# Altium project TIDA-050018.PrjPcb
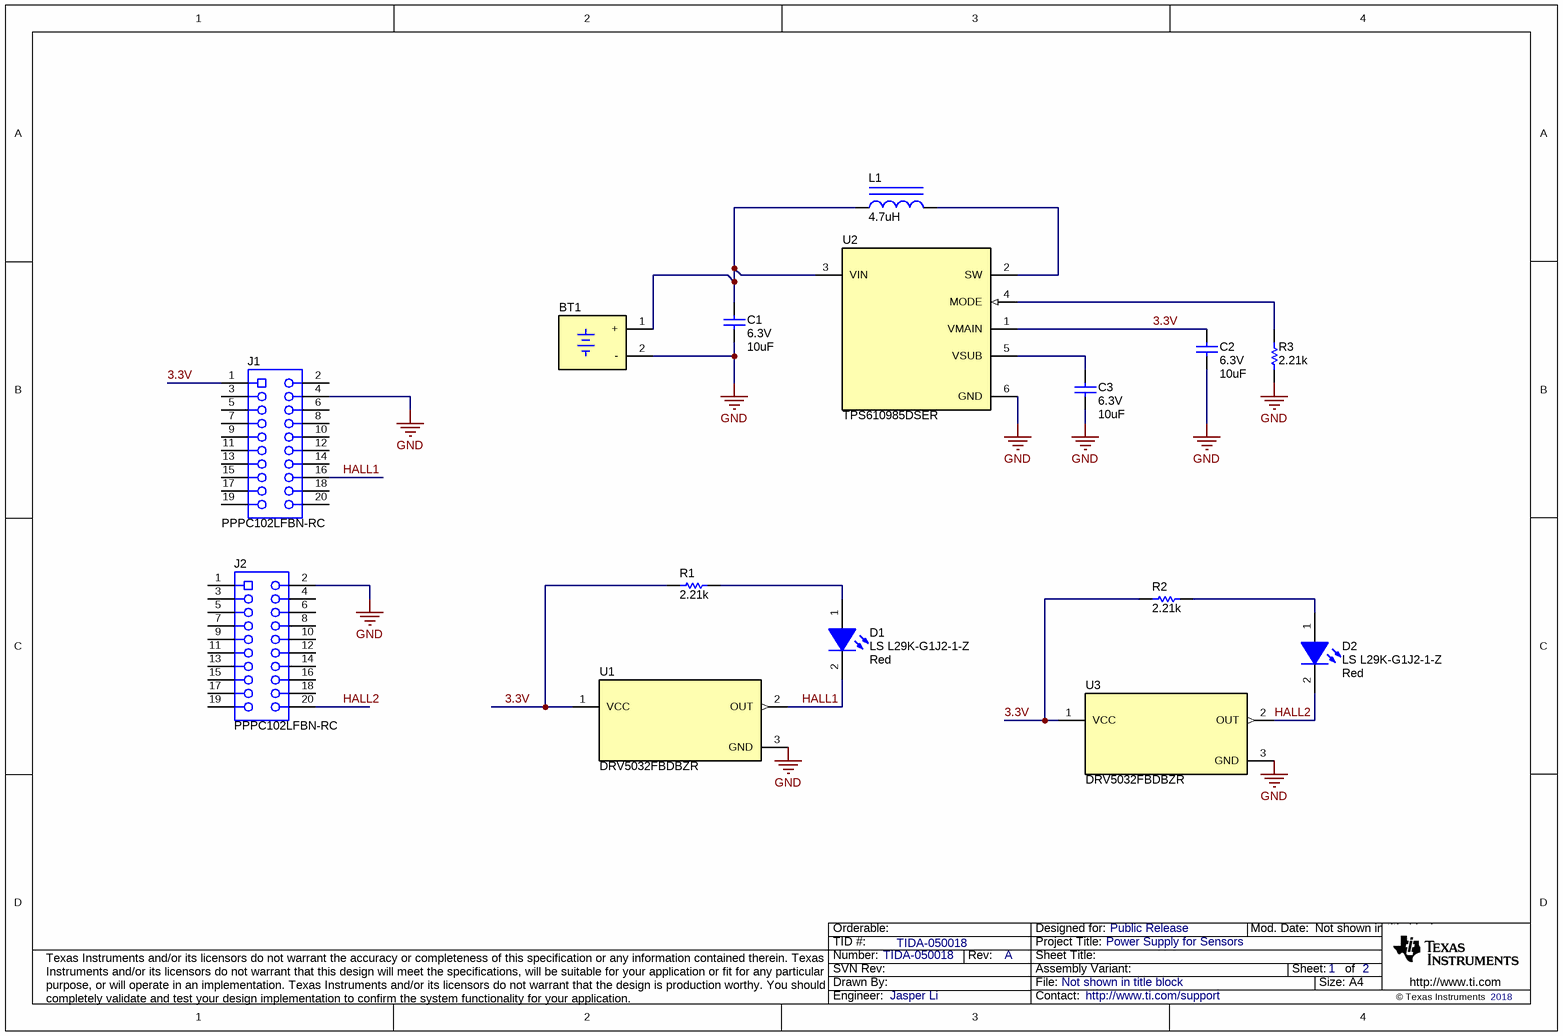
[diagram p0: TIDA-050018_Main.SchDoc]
CopyrightYear: 2018; PCB_Layout: Jasper Li; PCB_Rev: A; PRJ_Customer: Public Release; PRJ_Engineer: Jasper Li; PRJ_Number: TIDA-050018; PRJ_Title: Power Supply for Sensors; SCH_Rev: A; TechSupport: http://www.ti.com/support; TID: TIDA-050018
2 sheets, 20 parts. Net scope: global (net labels, ports and power ports of the same name join across sheets).
Board file: TIDA-050018_PCB.PcbDoc
Sheets:
  TIDA-050018_Main.SchDoc
  TIDA-050018_Hardware.SchDoc

## Sheet TIDA-050018_Main.SchDoc
size A4; Date: Not shown in title block; ApprovedBy: Not shown in title block; CheckedBy: Not shown in title block; Author: Not shown in title block; CompanyName: Not shown in title block; Engineer: Not shown in title block; Organization: Not shown in title block; Address1: Not shown in title block; Address2: Not shown in title block; Address3: Not shown in title block; Address4: Not shown in title block; DocumentNumber: 1; Revision: Use project parameter SCH_Rev; SheetNumber: 1; SheetTotal: 2; PageSetup: Record=PageOptions¦CenterHorizontal=True¦CenterVertical=True¦PrintScale=1.00¦XCorrection=1.00¦YCorrection=1.00¦PrintKind=0¦BorderSize=5000000¦LeftOffset=0¦BottomOffset=0¦Orientation=2¦PaperLength=1000¦PaperWidth=1000¦Scale=100¦PaperSource=15¦PrintQuality=600¦MediaType=1¦DitherType=10¦PaperKind=Letter¦PrintScaleMode=1

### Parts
BT1  1020  [Keystone_1020]  (value not drawn)
C1  VDC_V: 6.3V  ValueDisplayed: 10uF  [0603]  (hidden comment: GRM188R60J106ME47D)
C2  VDC_V: 6.3V  ValueDisplayed: 10uF  [0603]  (hidden comment: GRM188R60J106ME47D)
C3  VDC_V: 6.3V  ValueDisplayed: 10uF  [0603]  (hidden comment: GRM188R60J106ME47D)
D1  LS L29K-G1J2-1-Z  value Red  [LS L29K_Red]
D2  LS L29K-G1J2-1-Z  value Red  [LS L29K_Red]
J1  PPPC102LFBN-RC  [Sullins_PPPC102LFBN-RC]
J2  PPPC102LFBN-RC  [Sullins_PPPC102LFBN-RC]
L1  ValueDisplayed: 4.7uH  [DFE252012C]  (hidden comment: 1239AS-H-4R7M=P2)
R1  ValueDisplayed: 2.21k  [0603]  (hidden comment: RC0603FR-072K21L)
R2  ValueDisplayed: 2.21k  [0603]  (hidden comment: RC0603FR-072K21L)
R3  ValueDisplayed: 2.21k  [0603]  (hidden comment: RC0603FR-072K21L)
U1  DRV5032FBDBZR  [DBZ0003A_N]
U2  TPS610985DSER  [DSE0006A]
U3  DRV5032FBDBZR  [DBZ0003A_N]

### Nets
GND: BT1.2(-) C1.2 C2.2 C3.2 J1.4 J2.2 R3.1 U1.3(GND) U2.6(GND) U3.3(GND)
3.3V: C2.1 J1.1 R1.1 R2.1 U1.1(VCC) U2.1(VMAIN) U3.1(VCC)
HALL1: D1.2(K) J1.16 U1.2(OUT)
HALL2: D2.2(K) J2.20 U3.2(OUT)
NetBT1_1: BT1.1(+) C1.1 L1.1 U2.3(VIN)
NetC3_1: C3.1 U2.5(VSUB)
NetD1_1: D1.1(A) R1.2
NetD2_1: D2.1(A) R2.2
NetL1_2: L1.2 U2.2(SW)
NetR3_2: R3.2 U2.4(MODE)

Not connected (* = marked no-connect by the designer): J1 2 3 5 6 7 8 9 10 11 12 13 14 15 17 18 19 20; J2 1 3 4 5 6 7 8 9 10 11 12 13 14 15 16 17 18 19

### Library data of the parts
BT1 = CMP-0003908-1: HOLDER BATTERY AAA, SMT; Manufacturer: Keystone; CompType: Battery Holder
C1 C3 = CMP-0007303-5: CAP, CERM, 10 uF, 6.3 V, +/- 20%, X5R, 0603; Manufacturer: MuRata; TaMin_C: -55°C; ESR_ohm: 9m; Polarized: N; SizeAreaWB_mm2: 4.68; Value1: 0.009 ohm; U/M: EA; Value: 10uF; TaMax_C: 125°C; SizeZ_mm: 1; SizeX_mm: 1.6; SizeY_mm: 0.8; SizeArea_mm2: 1.28; Cap_F: 10µF; IRMS_A: 2.74A; AEC Category: Q200
C2 = CMP-0007303-5: CAP, CERM, 10 uF, 6.3 V, +/- 20%, X5R, 0603; Manufacturer: MuRata; TaMin_C: -55°C; ESR_ohm: 9m; Polarized: N; SizeAreaWB_mm2: 4.68; Value1: 0.009 ohm; U/M: EA; Value: 10uF; TaMax_C: 125°C; SizeZ_mm: 1; SizeX_mm: 1.6; SizeY_mm: 0.8; SizeArea_mm2: 1.28; CompType: Capacitor; Cap_F: 10µF; IRMS_A: 2.74A; AEC Category: Q200
D1 D2 = CMP-0002902-1: LED, Red, SMD; Manufacturer: OSRAM; Io_A: 20mA; Vr_V: 12V; Tjmax_C: 110°C; Value1: W; U/M: EA; Angle: 160; Vf_V: 1.8V
J1 J2 = CMP-0054642-1: Receptacle, 100mil, 10x2, Gold, TH; Manufacturer: Sullins Connector Solutions; CT: TRUE; Green_REACh: Incomplete; CompType: Socket Strip; CNHeader: FALSE; Green_Lifecycle: Not Set
L1 = CMP-0058899-1: Inductor, Shielded, Ferrite, 4.7 uH, 1.3 A, 0.2 ohm, SMD; Manufacturer: MuRata Toko; Isat: 1.5A @ 30% inductance drop; Irms: 1.3A @ 40C rise; SizeAreaWB_mm2: 11.84; DCR_ohm: 2d; Value1: 0.2 ohm; Value: 4.7uH; Imax_A: 1.3A; SizeZ_mm: 1.2; SizeX_mm: 2.7; SizeY_mm: 2.2; SizeArea_mm2: 5.94; Ind_H: 4.7µH; AEC Category: Q200
R1 R2 = CMP-0022984-5: RES, 2.21 k, 1%, 0.1 W, 0603; Manufacturer: Yageo; Power_W: 100mW; TempCo: 100 ppm/C; Value_Code: 2k21; Value: 2.21k; EIA_Code: E96; SizeX_mm: 1.6; SizeY_mm: 0.8; SizeZ_mm: 1; Value2: 0.1W; SizeArea_mm2: 1.28; AEC Qualified: N; VDC_V: 75V; AEC Category: Q200; SizeAreaWB_mm2: 4.68
R3 = CMP-0022984-5: RES, 2.21 k, 1%, 0.1 W, 0603; Manufacturer: Yageo; Power_W: 100mW; TempCo: 100 ppm/C; Value_Code: 2k21; Value: 2.21k; EIA_Code: E96; SizeX_mm: 1.6; SizeY_mm: 0.8; SizeZ_mm: 1; Value2: 0.1W; SizeArea_mm2: 1.28; CompType: Resistor; AEC Qualified: N; VDC_V: 75V; AEC Category: Q200; SizeAreaWB_mm2: 4.68
U1 U3 = CMP-0013239-4: Ultra-Low Power Digital-Switch Hall Effect Sensor, DBZ0003A (SOT-23-3); Manufacturer: Texas Instruments; SizeX_mm: 2.5; SizeY_mm: 3; CompType: IC; SizeZ_mm: 1.12; SizeArea_mm2: 7.5; SizeAreaWB_mm2: 14; U/M: EA; AEC Category: Q200; AEC Qualified: N
U2 = CMP-0074070-1: Ultra-Low Quiescent Current Synchronous Boost with Integrated LDO/Load, DSE0006A (WSON-6); Alternate PartNumber: TPS610985DSET; Alternate Manufacturer: Texas Instruments; Green_Lifecycle: Active; SizeAreaWB_mm2: 6.25; Green_REACh: Passed; U/M: EA; SizeZ_mm: 0.8; SizeX_mm: 1.5; SizeArea_mm2: 2.25; CompType: IC

## Sheet TIDA-050018_Hardware.SchDoc: EVM Hardware
size A4; Date: Not shown in title block; ApprovedBy: Not shown in title block; CheckedBy: Not shown in title block; Author: Not shown in title block; CompanyName: Not shown in title block; Engineer: Not shown in title block; Organization: Not shown in title block; Address1: Not shown in title block; Address2: Not shown in title block; Address3: Not shown in title block; Address4: Not shown in title block; DocumentNumber: 2; Revision: Use project parameter SCH_Rev; SheetNumber: 2; SheetTotal: 2; PageSetup: Record=PageOptions¦CenterHorizontal=True¦CenterVertical=True¦PrintScale=1.00¦XCorrection=1.00¦YCorrection=1.00¦PrintKind=0¦BorderSize=5000000¦LeftOffset=0¦BottomOffset=0¦Orientation=2¦PaperLength=1000¦PaperWidth=1000¦Scale=100¦PaperSource=15¦PrintQuality=600¦MediaType=1¦DitherType=10¦PaperKind=Letter¦PrintScaleMode=1
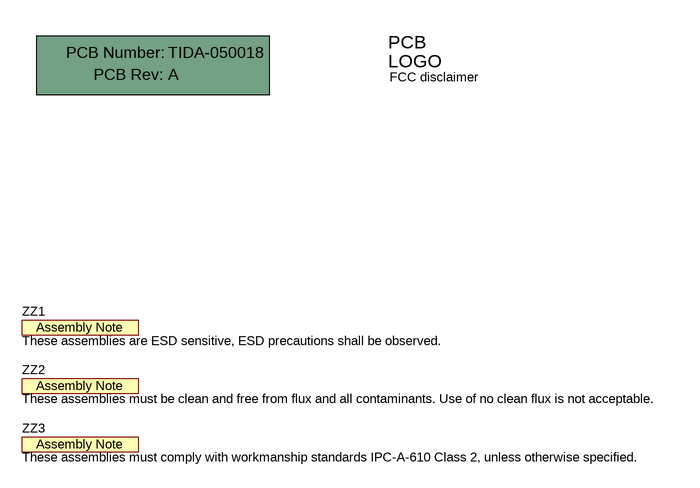
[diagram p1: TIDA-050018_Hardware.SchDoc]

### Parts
!PCB1  Printed Circuit Board  (value not drawn)  (mechanical)
Logo3  FCC disclaimer  [FCC_disclaimer]  (no BOM)
ZZ1  These assemblies are ESD sensitive, ESD precautions shall be observed.  [AssemblyNote]  (no BOM)
ZZ2  These assemblies must be clean and free from flux and all contaminants. Use of no clean flux is not acceptable.  [AssemblyNote]  (no BOM)
ZZ3  These assemblies must comply with workmanship standards IPC-A-610 Class 2, unless otherwise specified.  [AssemblyNote]  (no BOM)

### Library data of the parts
!PCB1 = CMP-0003618-2: Manufacturer: Any; PartNumber: TIDA-050018
Logo3 = CMP-0074847-1: FCC_disclaimer; Library Reference: Logo
ZZ1 = CMP-0077236-1
ZZ2 = CMP-0077237-1
ZZ3 = CMP-0077238-1

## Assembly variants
001: all parts fitted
